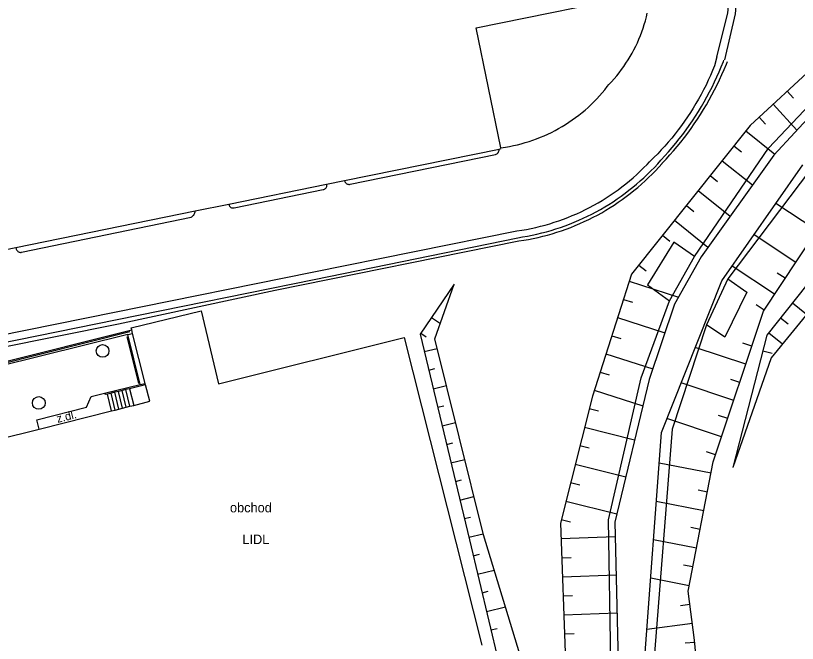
# Model space of a CAD drawing. Extents: x -538441 to -536770, y -1181008 to -1179809.
# Drawn here: x -537931.4 to -537869.9, y -1180097.6 to -1180048.3 of the extents above; entities that cross this region are included whole.
import ezdxf

# ---------------------------------------------------------------- set-up
doc = ezdxf.new("R2010")
doc.units = 0
for name, color, linetype in [('Vrstva 10', 7, 'Continuous'), ('Vrstva 11', 7, 'Continuous'), ('Vrstva 14', 7, 'Continuous'), ('Vrstva 15', 7, 'Continuous'), ('Vrstva 27', 7, 'Continuous'), ('Vrstva 40', 7, 'Continuous'), ('Vrstva 41', 7, 'Continuous'), ('Vrstva 5', 7, 'Continuous'), ('Vrstva 54', 7, 'Continuous'), ('Vrstva 9', 7, 'Continuous')]:
    doc.layers.add(name, color=color, linetype=linetype)

msp = doc.modelspace()

# ---------------------------------------------------------------- linework, layer by layer
at = {"layer": 'Vrstva 10'}
for p, q in [((-537905.1, -1180061.56), (-537893.67, -1180059.23)), ((-537914.24, -1180063.41), (-537907.23, -1180061.97)), ((-537930.95, -1180066.91), (-537917.62, -1180064.14)), ((-537954.08, -1180077.78), (-537923.66, -1180071.62)), ((-537953.94, -1180078.4), (-537923.43, -1180072.18)), ((-537953.89, -1180078.68), (-537923.33, -1180072.52)), ((-537937.55, -1180076.82), (-537922.291, -1180073.005)), ((-537922.61, -1180073.38), (-537937.52, -1180077.08))]:
    msp.add_line(p, q, dxfattribs=at)
for points in [[(-537876.26, -1180051.54), (-537875.4, -1180048.12), (-537875.12, -1180044.99)], [(-537884.76, -1180053.72), (-537884.55, -1180053.496), (-537884.345, -1180053.266), (-537884.146, -1180053.032), (-537883.954, -1180052.792), (-537883.768, -1180052.547), (-537883.588, -1180052.297), (-537883.415, -1180052.043), (-537883.249, -1180051.785), (-537883.089, -1180051.522), (-537882.937, -1180051.255), (-537882.791, -1180050.984), (-537882.652, -1180050.71), (-537882.521, -1180050.432), (-537882.397, -1180050.151), (-537882.28, -1180049.866), (-537882.171, -1180049.579), (-537882.069, -1180049.289), (-537881.975, -1180048.996), (-537881.888, -1180048.701), (-537881.809, -1180048.404), (-537881.738, -1180048.105)], [(-537876.26, -1180051.54), (-537876.444, -1180052.245), (-537876.602, -1180052.629), (-537876.767, -1180053.009), (-537876.94, -1180053.386), (-537877.12, -1180053.76), (-537877.307, -1180054.13), (-537877.501, -1180054.496), (-537877.702, -1180054.859), (-537877.911, -1180055.217), (-537878.126, -1180055.572), (-537878.348, -1180055.922), (-537878.576, -1180056.268), (-537878.811, -1180056.609), (-537879.053, -1180056.946), (-537879.301, -1180057.278), (-537879.556, -1180057.606), (-537879.817, -1180057.928), (-537880.084, -1180058.245), (-537880.357, -1180058.557), (-537880.636, -1180058.864), (-537880.921, -1180059.165), (-537881.212, -1180059.461), (-537881.508, -1180059.751), (-537881.57, -1180059.81)], [(-537880.65, -1180059.65), (-537880.352, -1180059.328), (-537880.06, -1180059.001), (-537879.774, -1180058.668), (-537879.494, -1180058.33), (-537879.22, -1180057.987), (-537878.952, -1180057.639), (-537878.691, -1180057.286), (-537878.437, -1180056.929), (-537878.189, -1180056.567), (-537877.947, -1180056.201), (-537877.713, -1180055.83), (-537877.485, -1180055.455), (-537877.264, -1180055.076), (-537877.049, -1180054.693), (-537876.842, -1180054.306), (-537876.642, -1180053.915), (-537876.45, -1180053.521), (-537876.264, -1180053.124), (-537876.086, -1180052.723), (-537875.915, -1180052.319), (-537875.751, -1180051.911), (-537875.712, -1180051.812)], [(-537880.56, -1180059.91), (-537880.255, -1180059.586), (-537879.957, -1180059.257), (-537879.664, -1180058.923), (-537879.378, -1180058.583), (-537879.097, -1180058.238), (-537878.823, -1180057.888), (-537878.555, -1180057.534), (-537878.294, -1180057.174), (-537878.039, -1180056.81), (-537877.79, -1180056.442), (-537877.549, -1180056.069), (-537877.314, -1180055.691), (-537877.086, -1180055.31), (-537876.865, -1180054.924), (-537876.65, -1180054.535), (-537876.443, -1180054.142), (-537876.243, -1180053.745), (-537876.05, -1180053.344), (-537875.865, -1180052.94), (-537875.686, -1180052.533), (-537875.515, -1180052.123), (-537875.43, -1180051.91)], [(-537893.255, -1180058.687), (-537892.895, -1180058.634), (-537892.582, -1180058.58), (-537892.27, -1180058.518), (-537891.96, -1180058.449), (-537891.651, -1180058.371), (-537891.345, -1180058.286), (-537891.041, -1180058.193), (-537890.739, -1180058.093), (-537890.44, -1180057.985), (-537890.144, -1180057.869), (-537889.851, -1180057.746), (-537889.561, -1180057.616), (-537889.274, -1180057.479), (-537888.991, -1180057.334), (-537888.711, -1180057.182), (-537888.436, -1180057.023), (-537888.164, -1180056.858), (-537887.897, -1180056.685), (-537887.635, -1180056.506), (-537887.376, -1180056.321), (-537887.123, -1180056.129), (-537886.874, -1180055.93), (-537886.631, -1180055.726), (-537886.393, -1180055.515), (-537886.16, -1180055.299), (-537885.933, -1180055.076), (-537885.711, -1180054.848), (-537885.495, -1180054.615), (-537885.285, -1180054.376), (-537885.081, -1180054.132), (-537884.884, -1180053.883), (-537884.76, -1180053.72)], [(-537893.67, -1180059.23), (-537893.618, -1180059.207), (-537893.569, -1180059.177), (-537893.525, -1180059.141), (-537893.487, -1180059.099), (-537893.455, -1180059.052), (-537893.43, -1180059), (-537893.412, -1180058.946), (-537893.402, -1180058.89), (-537893.399, -1180058.792)], [(-537891.99, -1180065.23), (-537891.617, -1180065.172), (-537891.246, -1180065.106), (-537890.876, -1180065.033), (-537890.507, -1180064.951), (-537890.141, -1180064.862), (-537889.776, -1180064.765), (-537889.414, -1180064.661), (-537889.053, -1180064.548), (-537888.696, -1180064.428), (-537888.341, -1180064.301), (-537887.988, -1180064.166), (-537887.639, -1180064.023), (-537887.293, -1180063.874), (-537886.95, -1180063.716), (-537886.61, -1180063.552), (-537886.274, -1180063.38), (-537885.942, -1180063.202), (-537885.613, -1180063.016), (-537885.289, -1180062.824), (-537884.968, -1180062.624), (-537884.652, -1180062.418), (-537884.341, -1180062.205), (-537884.034, -1180061.986), (-537883.731, -1180061.76), (-537883.434, -1180061.528), (-537883.142, -1180061.29), (-537882.854, -1180061.045), (-537882.572, -1180060.795), (-537882.296, -1180060.538), (-537882.024, -1180060.276), (-537881.759, -1180060.008), (-537881.57, -1180059.81)], [(-537891.93, -1180065.76), (-537891.55, -1180065.701), (-537891.171, -1180065.635), (-537890.793, -1180065.561), (-537890.418, -1180065.479), (-537890.044, -1180065.389), (-537889.672, -1180065.291), (-537889.302, -1180065.186), (-537888.934, -1180065.073), (-537888.569, -1180064.952), (-537888.206, -1180064.824), (-537887.846, -1180064.688), (-537887.489, -1180064.545), (-537887.135, -1180064.394), (-537886.784, -1180064.236), (-537886.437, -1180064.071), (-537886.093, -1180063.899), (-537885.753, -1180063.719), (-537885.416, -1180063.533), (-537885.084, -1180063.339), (-537884.755, -1180063.139), (-537884.431, -1180062.932), (-537884.111, -1180062.718), (-537883.796, -1180062.497), (-537883.486, -1180062.27), (-537883.18, -1180062.037), (-537882.879, -1180061.797), (-537882.583, -1180061.551), (-537882.292, -1180061.299), (-537882.007, -1180061.042), (-537881.727, -1180060.778), (-537881.453, -1180060.508), (-537881.184, -1180060.233), (-537880.921, -1180059.952), (-537880.664, -1180059.666), (-537880.65, -1180059.65)], [(-537891.84, -1180066.02), (-537891.46, -1180065.961), (-537891.081, -1180065.895), (-537890.703, -1180065.821), (-537890.328, -1180065.739), (-537889.954, -1180065.649), (-537889.582, -1180065.551), (-537889.212, -1180065.446), (-537888.844, -1180065.333), (-537888.479, -1180065.212), (-537888.116, -1180065.084), (-537887.756, -1180064.948), (-537887.399, -1180064.805), (-537887.045, -1180064.654), (-537886.694, -1180064.496), (-537886.347, -1180064.331), (-537886.003, -1180064.159), (-537885.663, -1180063.979), (-537885.326, -1180063.793), (-537884.994, -1180063.599), (-537884.665, -1180063.399), (-537884.341, -1180063.192), (-537884.021, -1180062.978), (-537883.706, -1180062.757), (-537883.396, -1180062.53), (-537883.09, -1180062.297), (-537882.789, -1180062.057), (-537882.493, -1180061.811), (-537882.202, -1180061.559), (-537881.917, -1180061.302), (-537881.637, -1180061.038), (-537881.363, -1180060.768), (-537881.094, -1180060.493), (-537880.831, -1180060.212), (-537880.574, -1180059.926), (-537880.56, -1180059.91)], [(-537907.23, -1180061.97), (-537907.181, -1180061.964), (-537907.134, -1180061.951), (-537907.09, -1180061.93), (-537907.05, -1180061.902), (-537907.014, -1180061.868), (-537906.985, -1180061.828), (-537906.963, -1180061.785), (-537906.947, -1180061.738), (-537906.94, -1180061.689), (-537906.941, -1180061.64), (-537906.949, -1180061.592), (-537906.967, -1180061.556)], [(-537905.556, -1180061.269), (-537905.52, -1180061.361), (-537905.492, -1180061.408), (-537905.458, -1180061.45), (-537905.418, -1180061.488), (-537905.373, -1180061.519), (-537905.323, -1180061.543), (-537905.271, -1180061.559), (-537905.217, -1180061.568), (-537905.163, -1180061.569), (-537905.1, -1180061.56)], [(-537914.642, -1180063.119), (-537914.633, -1180063.179), (-537914.618, -1180063.227), (-537914.595, -1180063.272), (-537914.566, -1180063.312), (-537914.531, -1180063.348), (-537914.49, -1180063.377), (-537914.446, -1180063.4), (-537914.398, -1180063.415), (-537914.349, -1180063.422), (-537914.299, -1180063.421), (-537914.24, -1180063.41)], [(-537917.62, -1180064.14), (-537917.561, -1180064.109), (-537917.506, -1180064.071), (-537917.457, -1180064.027), (-537917.413, -1180063.977), (-537917.375, -1180063.922), (-537917.344, -1180063.863), (-537917.32, -1180063.801), (-537917.304, -1180063.736), (-537917.292, -1180063.659)], [(-537923.66, -1180071.62), (-537908.1, -1180068.48), (-537891.99, -1180065.23)], [(-537923.43, -1180072.18), (-537907.95, -1180069.04), (-537891.93, -1180065.76)], [(-537923.33, -1180072.52), (-537911.02, -1180069.89), (-537891.84, -1180066.02)], [(-537931.408, -1180066.535), (-537931.375, -1180066.654), (-537931.351, -1180066.705), (-537931.321, -1180066.753), (-537931.285, -1180066.796), (-537931.243, -1180066.833), (-537931.196, -1180066.864), (-537931.145, -1180066.887), (-537931.091, -1180066.904), (-537931.036, -1180066.912), (-537930.979, -1180066.913), (-537930.95, -1180066.91)], [(-537929.567, -1180080.807), (-537929.76, -1180080.07), (-537925.86, -1180079.09), (-537925.49, -1180078.24), (-537924.43, -1180077.98)]]:
    msp.add_lwpolyline(points, dxfattribs=at)
at = {"layer": 'Vrstva 11'}
for p, q in [((-537875.39, -1180069), (-537877.07, -1180072.61)), ((-537924.43, -1180077.98), (-537921.62, -1180077.3)), ((-537922.435, -1180079.014), (-537922.744, -1180077.7)), ((-537923.89, -1180079.38), (-537924.2, -1180078.06)), ((-537923.599, -1180079.307), (-537923.909, -1180077.988)), ((-537923.308, -1180079.234), (-537923.618, -1180077.916)), ((-537923.017, -1180079.16), (-537923.326, -1180077.844)), ((-537922.726, -1180079.087), (-537923.035, -1180077.772))]:
    msp.add_line(p, q, dxfattribs=at)
for points in [[(-537875.63, -1180051.77), (-537874.81, -1180048.15), (-537874.569, -1180045.361), (-537874.54, -1180045.03)], [(-537878.03, -1180067.23), (-537879.64, -1180066.1), (-537881.72, -1180069.47)], [(-537881.72, -1180069.47), (-537879.98, -1180070.73), (-537878.03, -1180067.23)], [(-537875.39, -1180069), (-537873.92, -1180070.03), (-537875.63, -1180073.58), (-537877.07, -1180072.61)], [(-537922.46, -1180077.63), (-537922.744, -1180077.7), (-537923.035, -1180077.772), (-537923.326, -1180077.844), (-537923.618, -1180077.916), (-537923.909, -1180077.988), (-537924.2, -1180078.06)], [(-537921.196, -1180077.332), (-537922.46, -1180077.63), (-537922.13, -1180078.94)], [(-537924.2, -1180078.06), (-537924.39, -1180078.1), (-537924.43, -1180077.98)]]:
    msp.add_lwpolyline(points, dxfattribs=at)
at = {"layer": 'Vrstva 14'}
for p, q in [((-537864.31, -1180048.31), (-537873.64, -1180056.93)), ((-537872.2, -1180058.73), (-537863.86, -1180049.86)), ((-537863.68, -1180050.52), (-537871.78, -1180059.26)), ((-537873.64, -1180056.93), (-537882.98, -1180068.62)), ((-537878.03, -1180067.23), (-537872.2, -1180058.73)), ((-537871.78, -1180059.26), (-537877.51, -1180067.26)), ((-537875.87, -1180069.15), (-537869.5, -1180060.03)), ((-537868.91, -1180060.39), (-537875.39, -1180069)), ((-537872.6, -1180071.53), (-537866.5, -1180062.31)), ((-537864.17, -1180063.14), (-537872.33, -1180073.42)), ((-537863.28, -1180064.46), (-537871.99, -1180075.21)), ((-537877.51, -1180067.26), (-537879.587, -1180070.983)), ((-537882.98, -1180068.62), (-537886.06, -1180078.23)), ((-537896.92, -1180069.41), (-537899.61, -1180073.35)), ((-537898.45, -1180073.72), (-537896.92, -1180069.41)), ((-537880.63, -1180081.07), (-537875.87, -1180069.15)), ((-537882.22, -1180076.78), (-537879.98, -1180070.73)), ((-537879.587, -1180070.983), (-537881.6, -1180076.92)), ((-537876.55, -1180083.39), (-537872.6, -1180071.53)), ((-537877.07, -1180072.61), (-537879.79, -1180080.81)), ((-537899.61, -1180073.35), (-537895.73, -1180089.52)), ((-537894.63, -1180089.12), (-537898.45, -1180073.72)), ((-537872.33, -1180073.42), (-537875.02, -1180083.83)), ((-537871.99, -1180075.21), (-537875.02, -1180083.83)), ((-537884.8, -1180087.93), (-537882.22, -1180076.78)), ((-537881.6, -1180076.92), (-537884.29, -1180088.11)), ((-537886.06, -1180078.23), (-537888.57, -1180088.2)), ((-537882.083, -1180100.873), (-537880.63, -1180081.07)), ((-537879.79, -1180080.81), (-537881.353, -1180100.839)), ((-537878.53, -1180093.55), (-537876.55, -1180083.39)), ((-537884.581, -1180101.006), (-537884.8, -1180087.93)), ((-537884.29, -1180088.11), (-537883.988, -1180100.961)), ((-537888.57, -1180088.2), (-537888.09, -1180101.27)), ((-537891.07, -1180100.79), (-537894.63, -1180089.12)), ((-537895.73, -1180089.52), (-537893.22, -1180100.02))]:
    msp.add_line(p, q, dxfattribs=at)
msp.add_lwpolyline([(-537877.64, -1180102.46), (-537877.7, -1180100.67), (-537878.02, -1180097.4), (-537878.53, -1180093.55)], dxfattribs=at)
at = {"layer": 'Vrstva 15'}
for p, q in [((-537870.741, -1180054.252), (-537870.232, -1180054.803)), ((-537871.843, -1180055.27), (-537869.965, -1180057.302)), ((-537872.945, -1180056.288), (-537872.436, -1180056.839)), ((-537873.985, -1180057.362), (-537871.708, -1180059.182)), ((-537874.922, -1180058.534), (-537874.336, -1180059.002)), ((-537875.858, -1180059.706), (-537873.468, -1180061.616)), ((-537876.794, -1180060.878), (-537876.208, -1180061.346)), ((-537877.731, -1180062.05), (-537875.217, -1180064.058)), ((-537878.667, -1180063.222), (-537878.081, -1180063.69)), ((-537868.411, -1180065.199), (-537871.625, -1180063.073)), ((-537879.603, -1180064.394), (-537876.966, -1180066.501)), ((-537880.54, -1180065.566), (-537879.954, -1180066.034)), ((-537870.067, -1180067.701), (-537873.344, -1180065.533)), ((-537882.412, -1180067.909), (-537881.826, -1180068.378)), ((-537871.722, -1180070.203), (-537875.062, -1180067.993)), ((-537870.894, -1180068.952), (-537871.52, -1180068.538)), ((-537883.16, -1180069.182), (-537879.277, -1180070.427)), ((-537883.618, -1180070.611), (-537882.904, -1180070.84)), ((-537870.321, -1180070.889), (-537869.206, -1180071.774)), ((-537872.55, -1180071.454), (-537873.175, -1180071.04)), ((-537898.708, -1180072.029), (-537898.017, -1180072.501)), ((-537884.076, -1180072.039), (-537880.35, -1180073.233)), ((-537871.254, -1180072.064), (-537870.666, -1180072.53)), ((-537899.554, -1180073.268), (-537899.141, -1180073.55)), ((-537872.186, -1180073.239), (-537871.095, -1180074.105)), ((-537884.534, -1180073.468), (-537883.819, -1180073.696)), ((-537899.283, -1180074.712), (-537898.265, -1180074.467)), ((-537873.993, -1180075.713), (-537877.963, -1180074.391)), ((-537873.519, -1180074.29), (-537874.231, -1180074.053)), ((-537884.991, -1180074.896), (-537881.313, -1180076.075)), ((-537872.647, -1180074.648), (-537871.921, -1180074.836)), ((-537898.933, -1180076.17), (-537898.447, -1180076.054)), ((-537885.449, -1180076.324), (-537884.735, -1180076.553)), ((-537874.467, -1180077.136), (-537875.179, -1180076.899)), ((-537898.583, -1180077.629), (-537897.542, -1180077.379)), ((-537874.941, -1180078.559), (-537879.077, -1180077.182)), ((-537885.907, -1180077.753), (-537882.094, -1180078.975)), ((-537898.233, -1180079.088), (-537897.747, -1180078.971)), ((-537886.304, -1180079.199), (-537885.577, -1180079.382)), ((-537875.889, -1180081.406), (-537880.192, -1180079.973)), ((-537875.415, -1180079.982), (-537876.127, -1180079.745)), ((-537897.883, -1180080.546), (-537896.82, -1180080.291)), ((-537886.67, -1180080.653), (-537882.736, -1180081.644)), ((-537897.533, -1180082.005), (-537897.047, -1180081.888)), ((-537887.036, -1180082.108), (-537886.309, -1180082.291)), ((-537876.363, -1180082.829), (-537877.075, -1180082.592)), ((-537897.183, -1180083.463), (-537896.098, -1180083.203)), ((-537887.402, -1180083.563), (-537883.437, -1180084.561)), ((-537876.724, -1180084.282), (-537880.807, -1180083.486)), ((-537896.833, -1180084.922), (-537896.347, -1180084.805)), ((-537887.769, -1180085.017), (-537887.041, -1180085.2)), ((-537877.011, -1180085.754), (-537877.747, -1180085.61)), ((-537896.483, -1180086.381), (-537895.375, -1180086.115)), ((-537888.135, -1180086.472), (-537884.138, -1180087.478)), ((-537877.298, -1180087.226), (-537881.028, -1180086.499)), ((-537896.133, -1180087.839), (-537895.647, -1180087.723)), ((-537888.501, -1180087.926), (-537887.774, -1180088.109)), ((-537877.585, -1180088.699), (-537878.321, -1180088.555)), ((-537895.783, -1180089.298), (-537894.653, -1180089.027)), ((-537888.525, -1180089.417), (-537884.263, -1180089.26)), ((-537877.871, -1180090.171), (-537881.249, -1180089.513)), ((-537895.434, -1180090.757), (-537894.948, -1180090.64)), ((-537888.47, -1180090.916), (-537887.721, -1180090.888)), ((-537878.158, -1180091.643), (-537878.895, -1180091.5)), ((-537895.086, -1180092.216), (-537893.781, -1180091.904)), ((-537888.415, -1180092.415), (-537884.193, -1180092.26)), ((-537878.445, -1180093.115), (-537881.47, -1180092.526)), ((-537894.737, -1180093.674), (-537894.251, -1180093.558)), ((-537888.36, -1180093.914), (-537887.611, -1180093.886)), ((-537894.388, -1180095.133), (-537892.904, -1180094.778)), ((-537878.391, -1180094.598), (-537879.135, -1180094.697)), ((-537888.305, -1180095.413), (-537884.122, -1180095.259)), ((-537878.194, -1180096.085), (-537881.766, -1180096.558)), ((-537894.039, -1180096.592), (-537893.553, -1180096.476)), ((-537888.25, -1180096.912), (-537887.501, -1180096.884)), ((-537878.003, -1180097.573), (-537878.75, -1180097.646))]:
    msp.add_line(p, q, dxfattribs=at)
at = {"layer": 'Vrstva 27'}
for centre in [(-537924.58, -1180074.66), (-537929.6, -1180078.75)]:
    msp.add_circle(centre, 0.5, dxfattribs=at)
at = {"layer": 'Vrstva 5'}
for p, q in [((-537922.33, -1180072.85), (-537916.84, -1180071.52)), ((-537916.84, -1180071.52), (-537915.46, -1180077.26)), ((-537922.61, -1180073.38), (-537922.221, -1180073.282)), ((-537921.62, -1180077.3), (-537922.61, -1180073.38)), ((-537922.291, -1180073.005), (-537922.33, -1180072.85)), ((-537922.221, -1180073.282), (-537922.291, -1180073.005)), ((-537921.225, -1180077.216), (-537922.221, -1180073.282)), ((-537915.46, -1180077.26), (-537900.85, -1180073.6)), ((-537900.85, -1180073.6), (-537894.74, -1180097.8)), ((-537921.62, -1180077.3), (-537921.225, -1180077.216)), ((-537921.196, -1180077.332), (-537921.225, -1180077.216)), ((-537920.87, -1180078.62), (-537921.196, -1180077.332)), ((-537922.435, -1180079.014), (-537922.13, -1180078.94)), ((-537922.13, -1180078.94), (-537920.87, -1180078.62)), ((-537929.567, -1180080.807), (-537923.89, -1180079.38)), ((-537923.89, -1180079.38), (-537923.599, -1180079.307)), ((-537923.599, -1180079.307), (-537923.308, -1180079.234)), ((-537923.308, -1180079.234), (-537923.017, -1180079.16)), ((-537923.017, -1180079.16), (-537922.726, -1180079.087)), ((-537922.726, -1180079.087), (-537922.435, -1180079.014)), ((-537933.439, -1180081.78), (-537929.567, -1180080.807))]:
    msp.add_line(p, q, dxfattribs=at)
for points in [[(-537895.2, -1180049.27), (-537881.488, -1180046.45), (-537881.39, -1180046.43)], [(-537893.24, -1180058.76), (-537893.255, -1180058.687), (-537895.2, -1180049.27)], [(-537977.91, -1180069.349), (-537976.65, -1180075.75), (-537974.333, -1180075.278), (-537972.763, -1180074.958), (-537946.587, -1180069.626), (-537943.953, -1180069.09), (-537934.11, -1180067.085), (-537931.408, -1180066.535), (-537917.292, -1180063.659), (-537914.642, -1180063.119), (-537906.967, -1180061.556), (-537905.556, -1180061.269), (-537893.399, -1180058.792), (-537893.24, -1180058.76)]]:
    msp.add_lwpolyline(points, dxfattribs=at)
at = {"layer": 'Vrstva 54'}
msp.add_line((-537921.74, -1180077.23), (-537922.66, -1180073.55), dxfattribs=at)
at = {"layer": 'Vrstva 9'}
msp.add_line((-537953.03, -1180080.81), (-537922.43, -1180073.13), dxfattribs=at)

# ---------------------------------------------------------------- texts
at = {"layer": 'Vrstva 40'}
msp.add_text('z.dl.', height=0.65, rotation=14.10681, dxfattribs=at).set_placement((-537928.12, -1180080.324))
at = {"layer": 'Vrstva 41'}
for s, p in [('obchod', (-537914.563, -1180087.351)), ('LIDL', (-537913.585, -1180089.849))]:
    msp.add_text(s, height=0.75, dxfattribs=at).set_placement(p)

doc.saveas('drawing.dxf')
